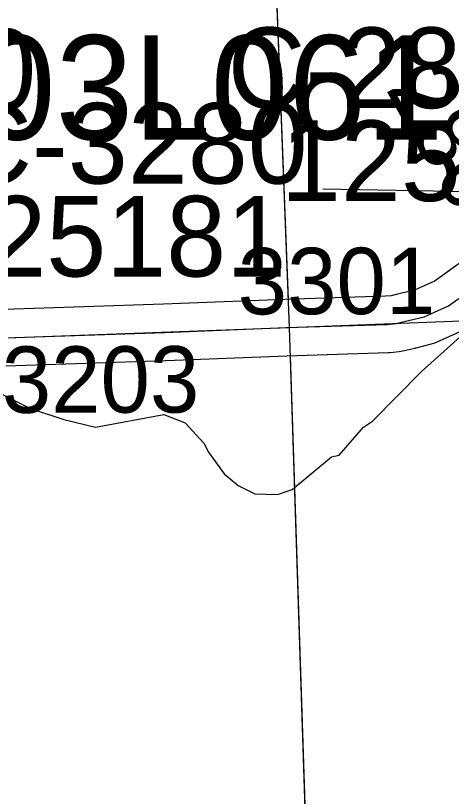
# Model space of a CAD drawing. Extents: x 128.7 to 185.5, y -21.4 to 12.6.
# Drawn here: x 147.675 to 148.134, y -0.77 to 0.053 of the extents above; entities that cross this region are included whole.
import ezdxf

# ---------------------------------------------------------------- set-up
doc = ezdxf.new("R2010")
doc.units = 0
for name, color, linetype in [('tdCoDirctArrow', 7, 'Continuous'), ('tdCoHydroRiver', 7, 'Continuous'), ('tdCoSecRdNmbr', 7, 'Continuous'), ('tdCoSecRteBand', 7, 'Continuous'), ('tdCoSecRteCL', 7, 'Continuous'), ('tdCoSectLine', 7, 'Continuous'), ('tdCoSectLinePart', 7, 'Continuous'), ('tdCoStrucPriMaintName', 7, 'Continuous'), ('tdCoStrucSecCoName', 7, 'Continuous'), ('tdCoStrucSecFHWANum', 7, 'Continuous'), ('tdCoSurfGravel', 7, 'Continuous')]:
    doc.layers.add(name, color=color, linetype=linetype)

msp = doc.modelspace()

# ---------------------------------------------------------------- linework, layer by layer
at = {"layer": 'tdCoDirctArrow'}
msp.add_line((147.99892, -0.12947), (148.48802, -0.13783), dxfattribs=at)
at = {"layer": 'tdCoHydroRiver'}
msp.add_lwpolyline([(147.63443, -0.33287), (147.69059, -0.36101), (147.72567, -0.37248), (147.75909, -0.38085), (147.83124, -0.36743), (147.85362, -0.37617), (147.87326, -0.39762), (147.8783, -0.40692), (147.89491, -0.43002), (147.90955, -0.44214), (147.92726, -0.45102), (147.951, -0.4518), (147.96663, -0.44654), (148.00818, -0.41201), (148.01602, -0.41017), (148.04188, -0.38086), (148.05113, -0.37422), (148.10306, -0.32192), (148.19811, -0.23655)], dxfattribs=at)
at = {"layer": 'tdCoSecRteBand'}
for points in [[(147.39934, -0.26597), (147.53142, -0.2613), (147.66258, -0.25637), (147.66264, -0.25637), (147.6627, -0.25637), (147.83105, -0.2507), (147.95872, -0.24577), (147.95882, -0.24577), (147.95891, -0.24576), (148.06485, -0.24235), (148.07138, -0.24166), (148.07809, -0.24014), (148.08229, -0.23919), (148.09575, -0.23572), (148.11636, -0.22661), (148.15007, -0.20262)], [(148.14341, -0.28025), (148.11776, -0.29159), (148.1155, -0.29259), (148.11311, -0.29321), (148.09683, -0.2974), (148.0964, -0.29751), (148.09597, -0.29761), (148.09134, -0.29866), (148.0829, -0.30057), (148.08118, -0.30096), (148.07942, -0.30114), (148.07005, -0.30213), (148.06896, -0.30224), (148.06787, -0.30228), (147.96094, -0.30573), (147.8333, -0.31066), (147.83322, -0.31066), (147.83315, -0.31066), (147.66477, -0.31633)]]:
    msp.add_lwpolyline(points, dxfattribs=at)
at = {"layer": 'tdCoSecRteCL'}
msp.add_lwpolyline([(147.66371, -0.28635), (147.83214, -0.28068), (147.95988, -0.27575), (148.06691, -0.2723), (148.07628, -0.27131), (148.08472, -0.2694), (148.08935, -0.26835), (148.10562, -0.26416), (148.13127, -0.25281), (148.16802, -0.22667)], dxfattribs=at)
at = {"layer": 'tdCoSectLine'}
for points in [[(147.92475, 0.72775), (147.96345, -0.27562)], [(147.96345, -0.27562), (148.96096, -0.23689)], [(146.96419, -0.31227), (147.96345, -0.27562)], [(147.96345, -0.27562), (147.99612, -1.28011)]]:
    msp.add_lwpolyline(points, dxfattribs=at)
at = {"layer": 'tdCoSectLinePart'}
for points in [[(147.93803, 0.38357), (147.9623, -0.24594)], [(147.96443, -0.30581), (147.98891, -1.05848)]]:
    msp.add_lwpolyline(points, dxfattribs=at)
at = {"layer": 'tdCoSurfGravel'}
for points in [[(148.08472, -0.2694), (148.08935, -0.26835), (148.10562, -0.26416), (148.13127, -0.25281), (148.16802, -0.22667), (148.23139, -0.1771), (148.28566, -0.13516)], [(147.38077, -0.29138), (147.38432, -0.29318), (147.38805, -0.29455), (147.39191, -0.29549), (147.39586, -0.29596), (147.39984, -0.29597), (147.53251, -0.29128), (147.66371, -0.28635), (147.83214, -0.28068), (147.95988, -0.27575), (148.06691, -0.2723), (148.07628, -0.27131), (148.08472, -0.2694)]]:
    msp.add_lwpolyline(points, dxfattribs=at)

# ---------------------------------------------------------------- texts
at = {"layer": 'tdCoSecRdNmbr'}
for s, rotation, p in [('2805', 299.31273, (148.06436, -0.02332)), ('3301', 0.11257, (147.90921, -0.26173)), ('3203', 0.11223, (147.66045, -0.36564))]:
    msp.add_text(s, height=0.07, rotation=rotation, dxfattribs=at).set_placement(p)
at = {"layer": 'tdCoStrucPriMaintName'}
msp.add_text('23503L061', height=0.11, dxfattribs=at).set_placement((147.38985, -0.0774))
msp.add_text('23503L061', height=0.11, dxfattribs=at).set_placement((147.38985, -0.0774))
msp.add_text('23503L061', height=0.11, dxfattribs=at).set_placement((147.38985, -0.0774))
at = {"layer": 'tdCoStrucSecCoName'}
for s, p in [('C-2849', (147.89859, -0.04419)), ('C-3280', (147.61014, -0.1238))]:
    msp.add_text(s, height=0.085, dxfattribs=at).set_placement(p)
at = {"layer": 'tdCoStrucSecFHWANum'}
for s, p in [('366940', (147.31737, -0.04589)), ('125150', (147.95471, -0.1422)), ('125181', (147.58086, -0.22181))]:
    msp.add_text(s, height=0.085, dxfattribs=at).set_placement(p)

doc.saveas('drawing.dxf')
